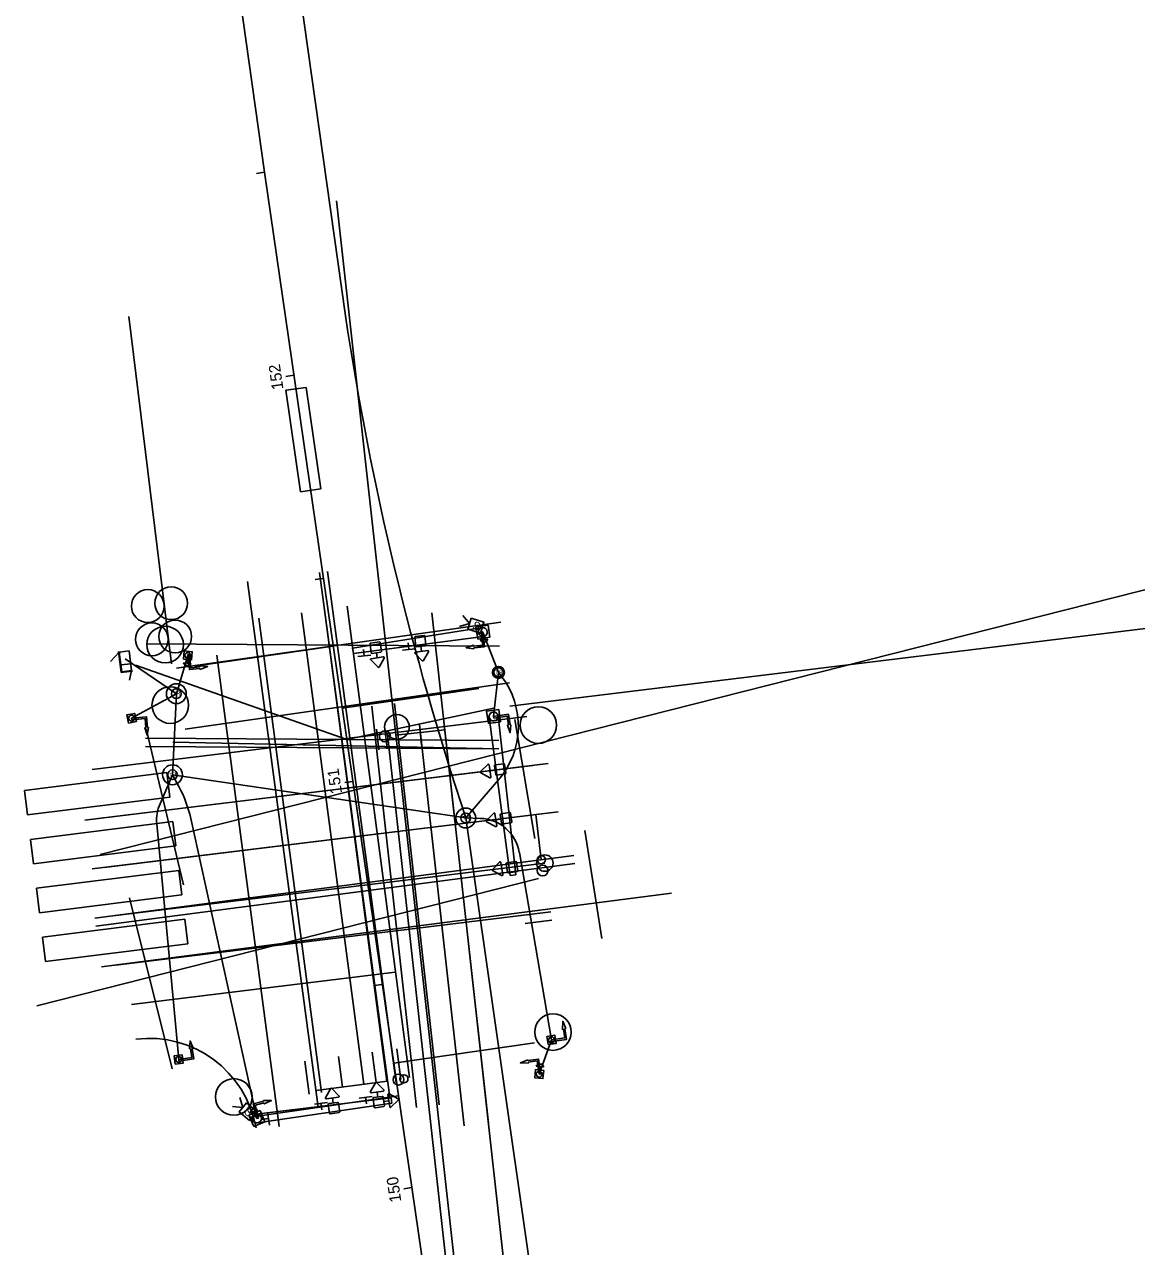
# Model space of a CAD drawing. Extents: x 1827063 to 1831280, y 711192 to 712800.
# Drawn here: x 1828041.8 to 1828313, y 711727.6 to 712025.4 of the extents above; entities that cross this region are included whole.
import ezdxf

# ---------------------------------------------------------------- set-up
doc = ezdxf.new("R2010")
doc.units = 0
for name, color, linetype in [('BR_P_Gen_Joint_Filler', 7, 'Continuous'), ('Default', 7, 'Continuous'), ('DR_P_Storm_Sewer', 7, 'Continuous'), ('GE_P_CL_50', 7, 'Continuous'), ('PV_P_Walk', 7, 'Continuous'), ('SC_Scratch6', 7, 'Continuous'), ('SG_X_Controllers', 7, 'Continuous'), ('SG_X_Detection', 7, 'Continuous'), ('SG_X_Interconnect_Cable', 7, 'Continuous'), ('UT_P_Water', 7, 'Continuous'), ('UT_P_Water_Cells', 7, 'Continuous'), ('UT_P_Water_Text', 7, 'Continuous'), ('UT_X_Misc_Cells', 7, 'Continuous'), ('VG_X_Cells', 7, 'Continuous')]:
    doc.layers.add(name, color=color, linetype=linetype)

# ---------------------------------------------------------------- blocks, each defined once
blk = doc.blocks.new('SPOLE_1')
at = {"layer": 'Default'}
blk.add_circle((0, 0), 0.0138, dxfattribs=at)
blk = doc.blocks.new('Sighead')
at = {"layer": 'Default'}
for p, q in [((-0.03, 0.975), (-0.335, 0.569)), ((0.335, 0.569), (0.03, 0.975)), ((-0.305, 0.508), (0.305, 0.508)), ((-0.254, -0.216), (-0.254, 0.216)), ((-0.216, 0.254), (0.216, 0.254)), ((0, 0.508), (0, 0.254)), ((0.254, 0.216), (0.254, -0.216)), ((0.216, -0.254), (-0.216, -0.254))]:
    blk.add_line(p, q, dxfattribs=at)
for centre, start, end in [((0, 0.953), 36.8699, 143.1301), ((-0.305, 0.546), 143.1301, 270), ((-0.216, 0.216), 90, 180), ((0.216, 0.216), 0, 90), ((0.305, 0.546), 270, 36.8699), ((-0.216, -0.216), 180, 270), ((0.216, -0.216), 270, 0)]:
    blk.add_arc(centre, 0.0381, start, end, dxfattribs=at)
blk = doc.blocks.new('A$C70A22DE5')
at = {"layer": 'Default'}
for p, q in [((0, 0), (0.476, 0)), ((0.476, 0.236), (0.476, -0.236))]:
    blk.add_line(p, q, dxfattribs=at)
blk.add_arc((0.369, 0), 0.259, 294.36008, 65.63992, dxfattribs=at)

msp = doc.modelspace()

# ---------------------------------------------------------------- linework, layer by layer
at = {"layer": 'BR_P_Gen_Joint_Filler'}
for p, q in [((1828067.24, 711954.24), (1828077.61, 711869.6)), ((1828114.93, 711882.79), (1828130.13, 711767.88)), ((1828120.49, 711883.67), (1828135.69, 711768.76)), ((1828098.95, 711880.68), (1828114.23, 711765.11)), ((1828109.36, 711882.05), (1828124.55, 711767.15)), ((1828088.72, 711871.72), (1828103.91, 711756.81)), ((1828137.4, 711761.51), (1828126.52, 711859.31)), ((1828142.87, 711762.11), (1828131.98, 711859.92)), ((1828164.3, 711856.77), (1828058.27, 711843.82)), ((1828154.93, 711757.69), (1828144.05, 711855.49)), ((1828128.21, 711848.63), (1828127.65, 711853.67)), ((1828130.2, 711848.85), (1828129.63, 711853.89)), ((1828148.97, 711757.03), (1828138.08, 711854.83)), ((1828138.64, 711849.79), (1828138.08, 711854.83)), ((1828165.76, 711844.85), (1828059.73, 711831.91)), ((1828167.21, 711832.94), (1828061.19, 711820)), ((1828168.67, 711821.03), (1828062.65, 711808.09)), ((1828170.12, 711809.12), (1828064.1, 711796.18)), ((1828170.36, 711807.14), (1828163.89, 711806.34)), ((1828132.2, 711794.42), (1828067.93, 711786.57)), ((1828126.54, 711774.97), (1828127.53, 711767.54)), ((1828132.62, 711775.77), (1828133.6, 711768.34)), ((1828110.19, 711772.8), (1828111.25, 711764.72)), ((1828118.36, 711773.89), (1828119.35, 711766.46))]:
    msp.add_line(p, q, dxfattribs=at)
for centre, radius in [((1828077.56, 711884.36), 4), ((1828071.86, 711883.67), 4), ((1828072.85, 711875.56), 4), ((1828078.56, 711876.26), 4), ((1828076.09, 711874.29), 4.46), ((1828077.34, 711859.53), 4.46), ((1828167.1, 711854.66), 4.46), ((1828132.62, 711854.22), 3), ((1828168.67, 711821.03), 2), ((1828170.66, 711779.86), 4.46), ((1828092.84, 711764.05), 4.46)]:
    msp.add_circle(centre, radius, dxfattribs=at)
at = {"layer": 'DR_P_Storm_Sewer'}
for p, q in [((1828100.32, 711989.38), (1828056.39, 712302.78)), ((1828100.32, 711989.38), (1828098.34, 711989.09)), ((1828182.93, 711420.35), (1828100.32, 711989.38)), ((1828107.5, 711939.9), (1828105.52, 711939.61)), ((1828114.69, 711890.42), (1828112.71, 711890.13)), ((1828121.87, 711840.94), (1828119.89, 711840.65)), ((1828129.05, 711791.45), (1828127.07, 711791.17)), ((1828136.24, 711741.97), (1828134.26, 711741.69))]:
    msp.add_line(p, q, dxfattribs=at)
at = {"layer": 'GE_P_CL_50'}
for p, q in [((1828157.91, 711879.78), (1828078.85, 711868.53)), ((1828157.63, 711873.88), (1828071.45, 711874.44)), ((1828120.39, 711851.12), (1828068.86, 711869.29)), ((1828160.02, 711864.93), (1828080.96, 711853.68)), ((1828156.26, 711858.81), (1828120.39, 711851.12)), ((1828157.47, 711848.88), (1828071.29, 711849.44)), ((1828157.48, 711850.88), (1828071.3, 711851.44)), ((1828157.47, 711848.88), (1828077.94, 711850.52))]:
    msp.add_line(p, q, dxfattribs=at)
at = {"layer": 'PV_P_Walk'}
for p, q in [((1829306.14, 712138.64), (1828060.23, 711823.14)), ((1828117.85, 711982.39), (1828154.28, 711655.03)), ((1828130.89, 711763.88), (1828113.74, 711891.83)), ((1828132.43, 711767.49), (1828115.72, 711892.09)), ((1828113.39, 711761.53), (1828096.2, 711889.68)), ((1828160.14, 711859.28), (1828381.92, 711886.36)), ((1828141.1, 711881.98), (1828166.21, 711656.36)), ((1828083.35, 711868.99), (1828117.09, 711873.89)), ((1828152.57, 711863.6), (1828119.28, 711858.76)), ((1828152.57, 711863.6), (1828152.57, 711863.6)), ((1828161.33, 711856.05), (1828166.2, 711827.02)), ((1828071.48, 711853.79), (1828080.54, 711815.77)), ((1828130.3, 711852.4), (1828152.3, 711654.81)), ((1828132.34, 711852.21), (1828144.26, 711853.54)), ((1828056.53, 711831.52), (1828169.47, 711845.31)), ((1828171.91, 711833.52), (1828058.33, 711819.65)), ((1828167.8, 711821.87), (1828166.46, 711832.85)), ((1828178.4, 711829), (1828182.54, 711802.69)), ((1828058.94, 711807.63), (1828175.75, 711822.9)), ((1828059.2, 711805.65), (1828176.01, 711820.92)), ((1828167.16, 711817.24), (1828044.77, 711786.25)), ((1828060.58, 711795.75), (1828199.53, 711813.72)), ((1828060.58, 711795.75), (1828199.53, 711813.72)), ((1828067.41, 711812.57), (1828077.81, 711770.91)), ((1828166.15, 711777.23), (1828131.84, 711772.25)), ((1828112.84, 711765.58), (1828130.35, 711767.92)), ((1828096.91, 711759.11), (1828132.99, 711764.35))]:
    msp.add_line(p, q, dxfattribs=at)
for centre, radius in [((1828129.69, 711851.92), 1.33), ((1828167.8, 711821.87), 1), ((1828168.13, 711819.22), 1.33), ((1828132.99, 711768.28), 1.33), ((1828134.31, 711768.46), 1)]:
    msp.add_circle(centre, radius, dxfattribs=at)
msp.add_arc((1828072.17, 711751.83), 26.5, 10.1696, 96.9614, dxfattribs=at)
at = {"layer": 'SC_Scratch6'}
for p, q in [((1828151.87, 711878.61), (1828154.84, 711879.04)), ((1828152.3, 711875.64), (1828151.87, 711878.61)), ((1828154.84, 711879.04), (1828155.27, 711876.07)), ((1828155.27, 711876.07), (1828152.3, 711875.64)), ((1828154.49, 711858.02), (1828157.46, 711858.46)), ((1828157.46, 711858.46), (1828157.9, 711855.48)), ((1828154.92, 711855.05), (1828154.49, 711858.02)), ((1828157.9, 711855.48), (1828154.92, 711855.05)), ((1828096.49, 711759.59), (1828099.25, 711760.78)), ((1828099.25, 711760.78), (1828100.44, 711758.02)), ((1828097.68, 711756.83), (1828096.49, 711759.59)), ((1828100.44, 711758.02), (1828097.68, 711756.83))]:
    msp.add_line(p, q, dxfattribs=at)
for points in [[(1828080.55, 711870.72), (1828080.73, 711872.72), (1828082.72, 711872.53), (1828082.54, 711870.54)], [(1828067.14, 711855.17), (1828066.74, 711857.13), (1828068.7, 711857.52), (1828069.1, 711855.56)], [(1828169.46, 711776.81), (1828169.17, 711778.79), (1828171.15, 711779.07), (1828171.44, 711777.09)], [(1828078.53, 711772.05), (1828078.29, 711774.04), (1828080.28, 711774.28), (1828080.52, 711772.29)], [(1828166.2, 711768.72), (1828166.41, 711770.71), (1828168.4, 711770.5), (1828168.19, 711768.51)]]:
    msp.add_lwpolyline(points, close=True, dxfattribs=at)
for centre in [(1828081.63, 711871.63), (1828067.92, 711856.35), (1828170.31, 711777.94), (1828079.41, 711773.16), (1828167.3, 711769.61)]:
    msp.add_circle(centre, 0.727, dxfattribs=at)
for centre, start, end in [((1828153.57, 711877.34), 98.2491, 278.2491), ((1828153.57, 711877.34), 278.2491, 98.2491), ((1828156.19, 711856.75), 98.2491, 278.2491), ((1828156.19, 711856.75), 278.2491, 98.2491), ((1828098.47, 711758.81), 113.3267, 293.3267), ((1828098.47, 711758.81), 293.3267, 113.3267)]:
    msp.add_arc(centre, 1.09, start, end, dxfattribs=at)
at = {"layer": 'SG_X_Controllers'}
for p, q in [((1828064.92, 711872.45), (1828062.76, 711870.13)), ((1828064.74, 711872.6), (1828065.37, 711867.47)), ((1828067.32, 711872.75), (1828064.92, 711872.45)), ((1828064.92, 711872.45), (1828065.51, 711867.66)), ((1828067.32, 711872.75), (1828067.91, 711867.95)), ((1828067.71, 711869.6), (1828065.31, 711869.31)), ((1828068.1, 711867.8), (1828065.37, 711867.47)), ((1828067.91, 711867.95), (1828065.51, 711867.66)), ((1828067.91, 711867.95), (1828067.37, 711865.59))]:
    msp.add_line(p, q, dxfattribs=at)
for centre in [(1828065.02, 711872.38), (1828067.82, 711868.02)]:
    msp.add_circle(centre, 0.0833, dxfattribs=at)
at = {"layer": 'SG_X_Detection'}
for p, q in [((1828110.45, 711936.96), (1828105.51, 711936.24)), ((1828105.51, 711936.24), (1828109.1, 711911.5)), ((1828114.05, 711912.22), (1828110.45, 711936.96)), ((1828109.1, 711911.5), (1828114.05, 711912.22)), ((1828147.85, 711878.66), (1828150.28, 711879.39)), ((1828148.7, 711881.38), (1828150.28, 711879.39)), ((1828076.51, 711843.08), (1828041.78, 711838.71)), ((1828077.26, 711837.13), (1828076.51, 711843.08)), ((1828041.78, 711838.71), (1828042.53, 711832.76)), ((1828042.53, 711832.76), (1828077.26, 711837.13)), ((1828077.96, 711831.17), (1828043.24, 711826.8)), ((1828078.71, 711825.22), (1828077.96, 711831.17)), ((1828043.24, 711826.8), (1828043.99, 711820.85)), ((1828043.99, 711820.85), (1828078.71, 711825.22)), ((1828079.42, 711819.26), (1828044.69, 711814.89)), ((1828080.17, 711813.3), (1828079.42, 711819.26)), ((1828044.69, 711814.89), (1828045.44, 711808.93)), ((1828045.44, 711808.93), (1828080.17, 711813.3)), ((1828080.87, 711807.35), (1828046.15, 711802.98)), ((1828081.62, 711801.39), (1828080.87, 711807.35)), ((1828046.15, 711802.98), (1828046.89, 711797.02)), ((1828046.89, 711797.02), (1828081.62, 711801.39)), ((1828094.34, 711763.92), (1828095.06, 711761.48)), ((1828092.53, 711761.73), (1828095.06, 711761.48))]:
    msp.add_line(p, q, dxfattribs=at)
for points in [[(1828150.71, 711880.74), (1828153.81, 711879.77), (1828152.96, 711877.06), (1828149.86, 711878.03)], [(1828095.96, 711762.58), (1828098.47, 711760.51), (1828096.66, 711758.32), (1828094.15, 711760.39)]]:
    msp.add_lwpolyline(points, close=True, dxfattribs=at)
at = {"layer": 'SG_X_Interconnect_Cable'}
for p, q in [((1828120.04, 711954.39), (1828078.87, 712247.62)), ((1828182.76, 711599.93), (1828149.39, 711832.03))]:
    msp.add_line(p, q, dxfattribs=at)
msp.add_arc((1828854.08, 712065.82), 742.45, 188.63128, 198.3536, dxfattribs=at)
at = {"layer": 'UT_P_Water'}
for p, q in [((1828157.37, 711867.5), (1828153.57, 711877.34)), ((1828078.83, 711862.32), (1828066.31, 711870.82)), ((1828078.83, 711862.32), (1828081.63, 711871.63)), ((1828157.37, 711867.5), (1828156.19, 711856.75)), ((1828078.83, 711862.32), (1828067.92, 711856.35)), ((1828078.83, 711862.32), (1828077.89, 711842.56)), ((1828074.84, 711835.51), (1828077.89, 711842.56)), ((1828077.89, 711842.56), (1828149.39, 711832.03)), ((1828079.45, 711839.66), (1828077.89, 711842.56)), ((1828098.47, 711758.81), (1828082.32, 711831.91)), ((1828149.39, 711832.03), (1828152.88, 711831.94)), ((1828079.41, 711773.16), (1828074.06, 711830.61)), ((1828170.31, 711777.94), (1828162.46, 711823.63)), ((1828170.31, 711777.94), (1828167.3, 711769.61))]:
    msp.add_line(p, q, dxfattribs=at)
for points in [[(1828158.06, 711866.61), (1828157.37, 711867.5)], [(1828149.39, 711832.03), (1828157.39, 711841.34)], [(1828149.39, 711832.03), (1828157.39, 711841.34)]]:
    msp.add_lwpolyline(points, dxfattribs=at)
for centre, radius, start, end in [((1828142.23, 711854.38), 20, 319.3008, 37.6982), ((1828142.23, 711854.38), 20, 319.3008, 37.6982), ((1828053.03, 711825.45), 30, 12.4499, 28.2869), ((1828084.02, 711831.54), 10, 156.6174, 185.3184), ((1828152.6, 711821.94), 10, 9.748, 88.3993)]:
    msp.add_arc(centre, radius, start, end, dxfattribs=at)
at = {"layer": 'UT_P_Water_Cells'}
for centre, radius in [((1828157.37, 711867.5), 1.46), ((1828157.37, 711867.5), 1.12), ((1828157.37, 711867.5), 1.12), ((1828157.37, 711867.5), 1.12), ((1828157.37, 711867.5), 1.12), ((1828157.37, 711867.5), 1.12), ((1828078.83, 711862.32), 2.42), ((1828078.83, 711862.32), 1.18), ((1828077.89, 711842.56), 2.42), ((1828077.89, 711842.56), 1.18), ((1828149.39, 711832.03), 2.42), ((1828149.39, 711832.03), 1.18)]:
    msp.add_circle(centre, radius, dxfattribs=at)
at = {"layer": 'UT_P_Water_Text'}
for p, q in [((1828121.81, 711873.4), (1828153.41, 711878.42)), ((1828153.73, 711876.26), (1828122, 711872.07)), ((1828122, 711872.07), (1828121.81, 711873.4)), ((1828160.26, 711817.98), (1828155.11, 711856.62)), ((1828157.28, 711856.89), (1828161.57, 711818.14)), ((1828161.57, 711818.14), (1828160.26, 711817.98)), ((1828098.32, 711759.89), (1828131.18, 711763.86)), ((1828131.18, 711763.86), (1828131.35, 711762.54)), ((1828131.35, 711762.54), (1828098.61, 711757.73))]:
    msp.add_line(p, q, dxfattribs=at)
for centre, start, end in [((1828153.57, 711877.34), 278.2888, 98.2888), ((1828156.19, 711856.75), 6.9777, 186.9777), ((1828098.47, 711758.81), 97.6532, 277.6532)]:
    msp.add_arc(centre, 1.09, start, end, dxfattribs=at)
at = {"layer": 'UT_X_Misc_Cells'}
for p, q in [((1828137.12, 711873.28), (1828133.94, 711872.92)), ((1828135.53, 711873.1), (1828135.36, 711874.69)), ((1828126.23, 711871.7), (1828123.05, 711871.34)), ((1828124.64, 711871.52), (1828124.47, 711873.11)), ((1828123.39, 711763.76), (1828126.56, 711764.19)), ((1828124.98, 711763.98), (1828125.19, 711762.39)), ((1828101.08, 711760.35), (1828101.51, 711757.18)), ((1828112.49, 711762.3), (1828115.66, 711762.73)), ((1828114.07, 711762.51), (1828114.29, 711760.93)), ((1828101.3, 711758.76), (1828099.71, 711758.55))]:
    msp.add_line(p, q, dxfattribs=at)
at = {"layer": 'VG_X_Cells'}
for p, q in [((1828153.15, 711877.34), (1828153.54, 711877.39)), ((1828082, 711871.87), (1828081.6, 711871.83)), ((1828067.96, 711855.95), (1828067.92, 711856.35)), ((1828156.25, 711856.36), (1828156.19, 711856.75)), ((1828170.31, 711777.94), (1828170.36, 711777.55)), ((1828079.41, 711773.16), (1828079.46, 711772.77)), ((1828167.3, 711769.61), (1828167.69, 711769.67)), ((1828098.85, 711758.91), (1828098.46, 711758.81))]:
    msp.add_line(p, q, dxfattribs=at)
for points in [[(1828151.32, 711873.87), (1828153.52, 711874.11), (1828153.15, 711877.34)], [(1828153.54, 711877.39), (1828153.96, 711873.76), (1828151.37, 711873.47)], [(1828151.39, 711873.23), (1828149.46, 711873.5), (1828151.3, 711874.1), (1828151.32, 711873.87)], [(1828151.37, 711873.47), (1828151.39, 711873.23)], [(1828081.6, 711871.83), (1828082.01, 711868.19), (1828084.6, 711868.49)], [(1828084.55, 711868.89), (1828082.36, 711868.64), (1828082, 711871.87)], [(1828084.63, 711868.25), (1828086.45, 711868.95), (1828084.53, 711869.12), (1828084.55, 711868.89)], [(1828084.6, 711868.49), (1828084.63, 711868.25)], [(1828067.92, 711856.35), (1828071.56, 711856.69), (1828071.79, 711854.09)], [(1828071.4, 711854.05), (1828071.2, 711856.25), (1828067.96, 711855.95)], [(1828156.19, 711856.75), (1828159.81, 711857.29), (1828160.19, 711854.71)], [(1828159.79, 711854.65), (1828159.47, 711856.84), (1828156.25, 711856.36)], [(1828072.03, 711854.11), (1828071.72, 711852.18), (1828071.16, 711854.03), (1828071.4, 711854.05)], [(1828071.79, 711854.09), (1828072.03, 711854.11)], [(1828160.42, 711854.74), (1828160.21, 711852.8), (1828159.56, 711854.62), (1828159.79, 711854.65)], [(1828160.19, 711854.71), (1828160.42, 711854.74)], [(1828173.82, 711780.7), (1828173.06, 711782.49), (1828172.96, 711780.56), (1828173.2, 711780.6)], [(1828173.2, 711780.6), (1828173.52, 711778.42), (1828170.31, 711777.94)], [(1828170.36, 711777.55), (1828173.98, 711778.08), (1828173.59, 711780.66)], [(1828173.59, 711780.66), (1828173.82, 711780.7)], [(1828082.3, 711775.82), (1828082.62, 711773.64), (1828079.41, 711773.16)], [(1828079.46, 711772.77), (1828083.08, 711773.3), (1828082.69, 711775.88)], [(1828082.93, 711775.92), (1828082.16, 711777.71), (1828082.06, 711775.78), (1828082.3, 711775.82)], [(1828082.69, 711775.88), (1828082.93, 711775.92)], [(1828164.53, 711773.12), (1828162.74, 711772.36), (1828164.67, 711772.26), (1828164.63, 711772.49)], [(1828164.57, 711772.89), (1828164.53, 711773.12)], [(1828167.69, 711769.67), (1828167.15, 711773.28), (1828164.57, 711772.89)], [(1828164.63, 711772.49), (1828166.82, 711772.83), (1828167.3, 711769.61)], [(1828098.46, 711758.81), (1828097.57, 711762.35), (1828100.1, 711762.99)], [(1828100.1, 711762.99), (1828100.05, 711763.22)], [(1828100.05, 711763.22), (1828101.99, 711763.2), (1828100.25, 711762.37), (1828100.2, 711762.6)], [(1828100.2, 711762.6), (1828098.05, 711762.06), (1828098.85, 711758.91)]]:
    msp.add_lwpolyline(points, dxfattribs=at)

# ---------------------------------------------------------------- block references
at = {"layer": 'SC_Scratch6'}
for p, xscale, yscale, rotation in [((1828081.63, 711871.63), 52.49554118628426, 52.49554118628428, 84.72243063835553), ((1828067.92, 711856.35), 52.495541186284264, 52.49554118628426, 101.47221809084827), ((1828170.31, 711777.94), 52.49554118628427, 52.49554118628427, 98.21763858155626), ((1828079.41, 711773.16), 52.49554118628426, 52.49554118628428, 96.87801239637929), ((1828167.3, 711769.61), 52.495541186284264, 52.49554118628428, 83.82036321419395)]:
    msp.add_blockref('SPOLE_1', p, dxfattribs=dict(at, xscale=xscale, yscale=yscale, rotation=rotation))
at = {"layer": 'SG_X_Detection'}
for p, xscale, yscale, rotation in [((1828153.57, 711877.34), 3.9417244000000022, 3.9417244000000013, -81.75093848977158), ((1828081.63, 711871.63), 3.9417244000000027, 3.9417244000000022, -95.2775693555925), ((1828167.3, 711769.61), 3.941724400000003, 3.9417244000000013, 83.82036322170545), ((1828098.47, 711758.81), 3.941724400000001, 3.9417244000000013, 113.3266563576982)]:
    msp.add_blockref('A$C70A22DE5', p, dxfattribs=dict(at, xscale=xscale, yscale=yscale, rotation=rotation))
at = {"layer": 'UT_P_Water'}
for p, xscale, yscale, rotation in [((1828138.32, 711875.12), 4.921250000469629, 4.92125000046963, -172.91499701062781), ((1828127.44, 711873.54), 4.92125000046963, 4.92125000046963, -171.59372885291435), ((1828157.77, 711843.87), 4.92125000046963, 4.92125000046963, 98.40627114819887), ((1828159.21, 711831.96), 4.92125000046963, 4.92125000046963, 98.40627114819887), ((1828160.67, 711820.05), 4.92125000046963, 4.92125000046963, 98.40627114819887), ((1828117.26, 711761.33), 4.921250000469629, 4.9212500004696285, 8.406271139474), ((1828128.16, 711762.79), 4.921250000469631, 4.921250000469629, 7.872378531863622), ((1828128.16, 711762.79), 4.921250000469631, 4.92125000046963, -82.12762146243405)]:
    msp.add_blockref('Sighead', p, dxfattribs=dict(at, xscale=xscale, yscale=yscale, rotation=rotation))

# ---------------------------------------------------------------- texts
at = {"layer": 'DR_P_Storm_Sewer'}
for s, p in [('152', (1828104.95, 711936.58)), ('151', (1828119.25, 711838.07)), ('150', (1828133.7, 711738.59))]:
    msp.add_text(s, height=2.8, rotation=98.2605, dxfattribs=at).set_placement(p)
at = {"layer": 'SG_X_Detection'}
for rotation, p in [(342.5748, (1828150.92, 711878.17)), (320.4315, (1828095.19, 711760.11))]:
    msp.add_text('S', height=1.95, rotation=rotation, dxfattribs=at).set_placement(p)
at = {"layer": 'UT_P_Water_Cells'}
for rotation, p in [(356.5528, (1828156.54, 711867.06)), (3.7551, (1828078.06, 711861.79)), (3.7551, (1828077.12, 711842.03)), (3.7551, (1828148.62, 711831.5))]:
    msp.add_text('TR', height=0.962, rotation=rotation, dxfattribs=at).set_placement(p)

doc.saveas('drawing.dxf')
